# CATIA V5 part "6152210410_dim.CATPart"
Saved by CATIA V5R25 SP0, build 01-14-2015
Part number: 6152210410_dim
Source: made
Property "PROI_CREATED_ON": "12/17/2008 9:21:37 AM"
Property "BLANK_DRAWING": "--"
Property "DRAWN_BY": "ALG"
Property "FINISH": "--"
Property "HEAT_TREATMENT": "ASSIGN"
Property "MATERIAL": "ASSIGN"
Property "PROJECT": "--"
Property "PROTOTYPE_NO": "--"
Property "RELATED_DRAWING": "--"
Property "COMPLETE_MATERIAL": "ASSIGN-ASSIGN"
Property "DESCRIPTION": "Q-AUDIT 150"
Property "DRAWING_EXIST": "--"
Property "MANUFACTURER": "--"
Property "MANUFACTURER_2": "--"
Property "MANUFACTURER_REF": "--"
Property "TYPE_PART": "A"
Property "TODAY_DATE": "2021/12/06"
Property "PDMREV": "01.0"
Property "PDMRL": "Production"
Property "PROI_REVISION": "01"
Property "PROI_VERSION": "0"
Property "PROI_RELEASE": "Production"
Property "PTC_MODIFIED": false
Property "MFG_WP_MATERIAL": "ASSIGN"
Property "COMPANY_CODE": "---"
Property "DESCRIPTION_JP": "--"
Property "PQP_DOCUMENT": "--"
Property "SUPPLIER": "--"
Property "REFERENCE": "6152210410"
Property "PTC_WM_REVISION": "01"
Property "PTC_WM_ITERATION": "0"
Property "PTC_WM_VERSION": "01.0"
Property "PTC_WM_LIFECYCLE_STATE": "Production"
Property "PTC_WM_LIFECYCLE": "Design_Process"
Property "PTC_WM_LOCATION": "/Products/TORQUE MEASUREMENT SYSTEMS/A3020 - Q-AUDIT/9-01-Dimensional Drawings a"
Property "PTC_WM_CREATED_BY": "Alain Le Goc (grealg) (grealg: CPD)"
Property "PTC_WM_CREATED_ON": "06-Dec-21 01:59:18 PM"
Property "PTC_WM_MODIFIED_BY": "Alain Le Goc (grealg) (grealg: CPD)"
Property "PTC_WM_MODIFIED_ON": "06-Dec-21 03:58:28 PM"
Property "PTC_WM_TEAM": "Default"
Property "PTC_ORGANIZATION_ID": "CPD"
Property "EXPORT_CONTROL": "NULL"
Property "PTC_WM_NAME": "6152210410_dim.prt"
Property "PTC_WM_NUMBER": "6152210410_DIM.PRT"
Property "PTC_COMMON_NAME": "6152210410_dim.prt"
Property "PTC_MASTER_MATERIAL": "ASSIGN"
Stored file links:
  d:\ptc\Echange\temp\6152210410_dim.CATPart

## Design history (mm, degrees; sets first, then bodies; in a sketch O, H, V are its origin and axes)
AxisSystem1 "CS0": origin (0, 0, 0), X (1, 0, 0), Y (0, 1, 0), Z (0, 0, 1)
Set1
  DatumSurface1 "Sheet.1"
  DatumSurface2 "Sheet.2"
  DatumSurface3 "Sheet.3"
  DatumSurface4 "Sheet.4"
  DatumSurface5 "Sheet.5"
  DatumSurface6 "Sheet.6"
  DatumSurface7 "Sheet.7"
  DatumSurface8 "Sheet.8"
  DatumSurface9 "Sheet.9"
  DatumSurface10 "Sheet.10"
  DatumSurface11 "Sheet.11"
  DatumSurface12 "Sheet.12"
  DatumSurface13 "Sheet.13"
  DatumSurface14 "Sheet.14"
  DatumSurface15 "Sheet.15"
  DatumSurface16 "Sheet.16"
  DatumSurface17 "Sheet.17"
  DatumSurface18 "Sheet.18"
  DatumSurface19 "Sheet.19"
  DatumSurface20 "Sheet.20"
  DatumSurface21 "Sheet.21"
  DatumSurface22 "Sheet.22"
  DatumSurface23 "Sheet.23"
  DatumSurface24 "Sheet.24"
  DatumSurface25 "Sheet.25"
  Plane1 "RIGHT": stored without definition
  Plane2 "TOP": stored without definition
  Plane3 "FRONT": stored without definition
Body1 "PartBody" (main body)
